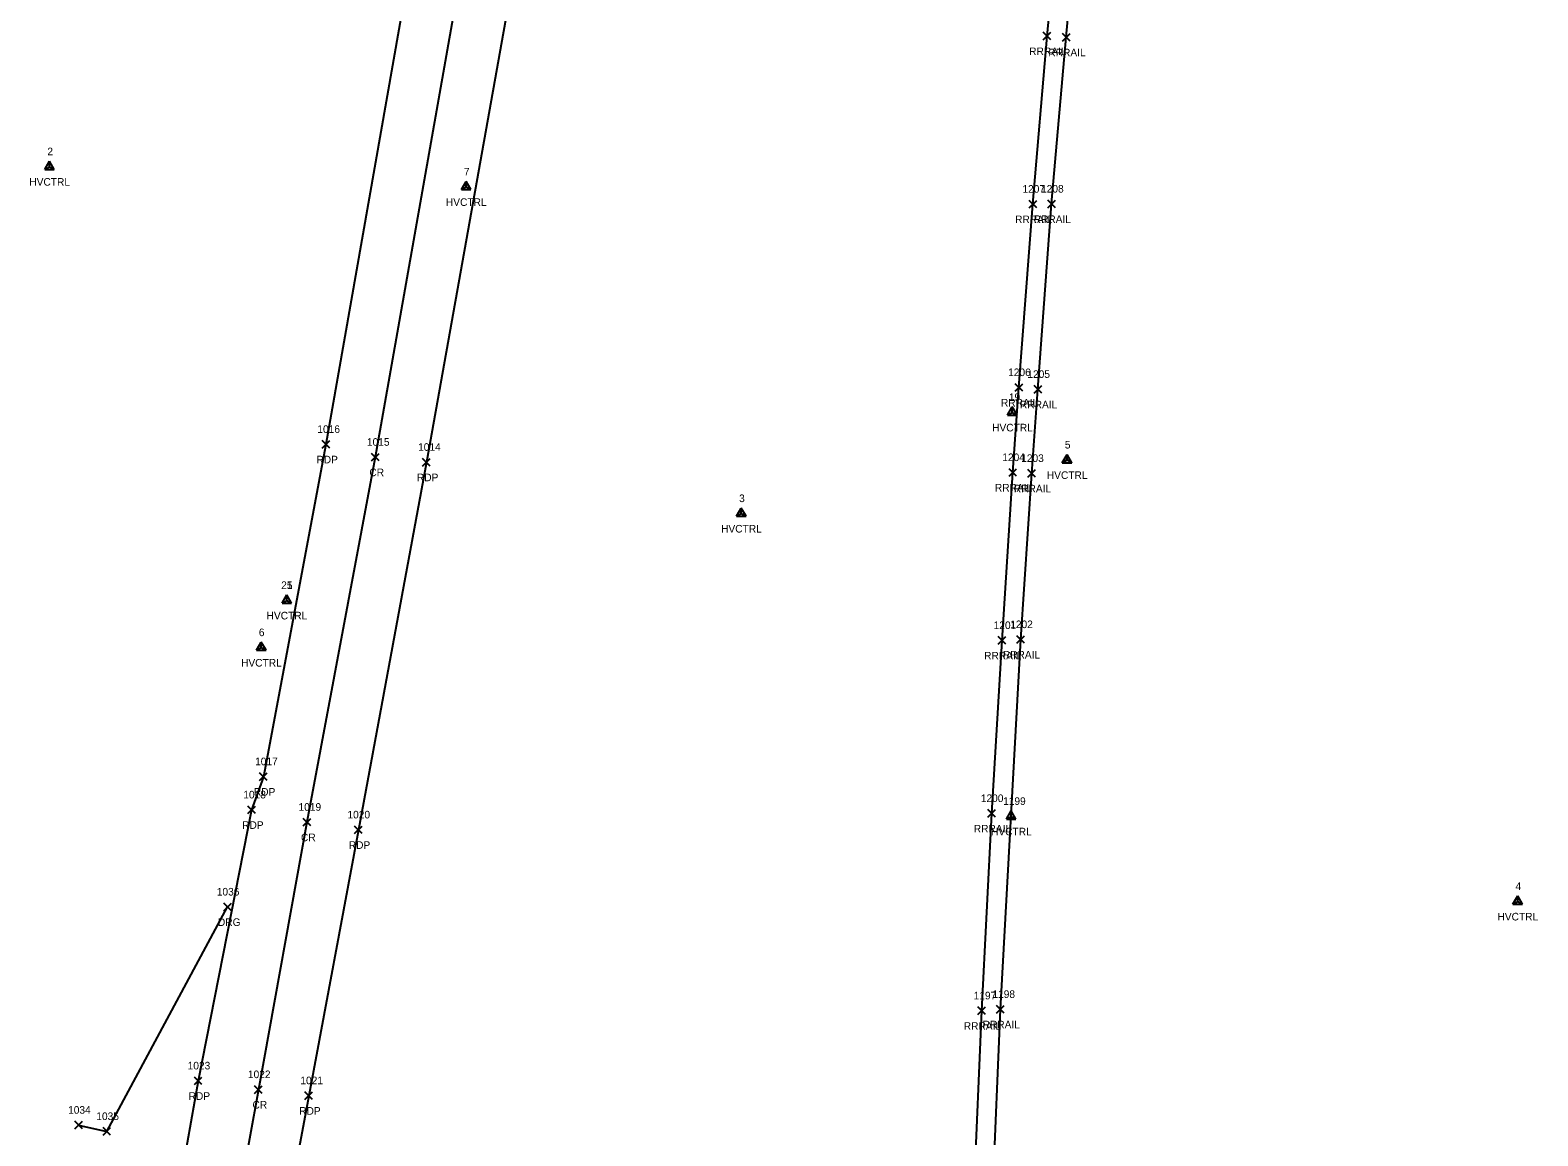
# Model space of a CAD drawing. Extents: x 1754529 to 1755810, y 621660 to 624656.
# Drawn here: x 1755360 to 1755756.4, y 623410 to 623700.7 of the extents above; entities that cross this region are included whole.
import ezdxf

# ---------------------------------------------------------------- set-up
doc = ezdxf.new("R2010")
doc.units = 0
for name, color, linetype in [('C_A', 7, 'Continuous'), ('C_I', 7, 'Continuous'), ('CPSM', 7, 'Continuous'), ('Level 14', 7, 'Continuous'), ('P_A', 7, 'Continuous'), ('P_I', 7, 'Continuous'), ('PET', 7, 'Continuous'), ('PRC', 7, 'Continuous'), ('R_A', 7, 'Continuous'), ('R_I', 7, 'Continuous'), ('R_TIC', 7, 'Continuous'), ('RDG', 7, 'Continuous'), ('RR', 7, 'Continuous')]:
    doc.layers.add(name, color=color, linetype=linetype)

msp = doc.modelspace()

# ---------------------------------------------------------------- linework, layer by layer
at = {"layer": 'CPSM'}
for p, q in [((1755363.86, 623664.07), (1755365.11, 623666.24)), ((1755363.86, 623664.07), (1755365.11, 623666.24)), ((1755366.36, 623664.07), (1755365.11, 623666.24)), ((1755365.12, 623664.79), (1755365.11, 623666.24)), ((1755366.36, 623664.07), (1755365.11, 623666.24)), ((1755365.12, 623664.79), (1755365.11, 623666.24)), ((1755363.86, 623664.07), (1755365.12, 623664.79)), ((1755363.86, 623664.07), (1755365.12, 623664.79)), ((1755363.86, 623664.07), (1755366.36, 623664.07)), ((1755363.86, 623664.07), (1755366.36, 623664.07)), ((1755365.12, 623664.79), (1755365.12, 623664.79)), ((1755365.12, 623664.79), (1755366.36, 623664.07)), ((1755365.12, 623664.79), (1755365.12, 623664.79)), ((1755365.12, 623664.79), (1755366.36, 623664.07)), ((1755473.39, 623658.75), (1755474.64, 623660.91)), ((1755473.39, 623658.75), (1755474.64, 623659.47)), ((1755473.39, 623658.75), (1755475.89, 623658.75)), ((1755475.89, 623658.75), (1755474.64, 623660.91)), ((1755474.64, 623659.47), (1755474.64, 623660.91)), ((1755474.64, 623659.47), (1755474.64, 623659.47)), ((1755474.64, 623659.47), (1755475.89, 623658.75)), ((1755617, 623599.48), (1755618.25, 623601.65)), ((1755617, 623599.48), (1755618.25, 623600.2)), ((1755617, 623599.48), (1755619.5, 623599.48)), ((1755619.5, 623599.48), (1755618.25, 623601.65)), ((1755618.25, 623600.2), (1755618.25, 623601.65)), ((1755618.25, 623600.2), (1755618.25, 623600.2)), ((1755618.25, 623600.2), (1755619.5, 623599.48)), ((1755631.38, 623586.98), (1755632.63, 623589.15)), ((1755631.38, 623586.98), (1755632.63, 623587.7)), ((1755631.38, 623586.98), (1755633.88, 623586.98)), ((1755633.88, 623586.98), (1755632.63, 623589.15)), ((1755632.63, 623587.7), (1755632.63, 623589.15)), ((1755632.63, 623587.7), (1755632.63, 623587.7)), ((1755632.63, 623587.7), (1755633.88, 623586.98)), ((1755545.73, 623572.9), (1755546.98, 623575.07)), ((1755548.23, 623572.9), (1755546.98, 623575.07)), ((1755546.98, 623573.63), (1755546.98, 623575.07)), ((1755545.73, 623572.9), (1755546.98, 623573.63)), ((1755545.73, 623572.9), (1755548.23, 623572.9)), ((1755546.98, 623573.63), (1755546.98, 623573.63)), ((1755546.98, 623573.63), (1755548.23, 623572.9)), ((1755426.24, 623550.06), (1755427.49, 623552.22)), ((1755426.26, 623550.07), (1755427.51, 623552.23)), ((1755426.26, 623550.07), (1755427.51, 623552.23)), ((1755426.26, 623550.07), (1755427.51, 623552.23)), ((1755426.26, 623550.07), (1755427.51, 623552.23)), ((1755426.26, 623550.07), (1755427.51, 623552.23)), ((1755428.74, 623550.06), (1755427.49, 623552.22)), ((1755427.49, 623550.78), (1755427.49, 623552.22)), ((1755428.76, 623550.07), (1755427.51, 623552.23)), ((1755427.51, 623550.79), (1755427.51, 623552.23)), ((1755428.76, 623550.07), (1755427.51, 623552.23)), ((1755427.51, 623550.79), (1755427.51, 623552.23)), ((1755428.76, 623550.07), (1755427.51, 623552.23)), ((1755427.51, 623550.79), (1755427.51, 623552.23)), ((1755428.76, 623550.07), (1755427.51, 623552.23)), ((1755427.51, 623550.79), (1755427.51, 623552.23)), ((1755428.76, 623550.07), (1755427.51, 623552.23)), ((1755427.51, 623550.79), (1755427.51, 623552.23)), ((1755426.24, 623550.06), (1755427.49, 623550.78)), ((1755426.24, 623550.06), (1755428.74, 623550.06)), ((1755426.26, 623550.07), (1755427.51, 623550.79)), ((1755426.26, 623550.07), (1755427.51, 623550.79)), ((1755426.26, 623550.07), (1755427.51, 623550.79)), ((1755426.26, 623550.07), (1755427.51, 623550.79)), ((1755426.26, 623550.07), (1755427.51, 623550.79)), ((1755426.26, 623550.07), (1755428.76, 623550.07)), ((1755426.26, 623550.07), (1755428.76, 623550.07)), ((1755426.26, 623550.07), (1755428.76, 623550.07)), ((1755426.26, 623550.07), (1755428.76, 623550.07)), ((1755426.26, 623550.07), (1755428.76, 623550.07)), ((1755427.49, 623550.78), (1755427.49, 623550.78)), ((1755427.49, 623550.78), (1755428.74, 623550.06)), ((1755427.51, 623550.79), (1755427.51, 623550.79)), ((1755427.51, 623550.79), (1755428.76, 623550.07)), ((1755427.51, 623550.79), (1755427.51, 623550.79)), ((1755427.51, 623550.79), (1755428.76, 623550.07)), ((1755427.51, 623550.79), (1755427.51, 623550.79)), ((1755427.51, 623550.79), (1755428.76, 623550.07)), ((1755427.51, 623550.79), (1755427.51, 623550.79)), ((1755427.51, 623550.79), (1755428.76, 623550.07)), ((1755427.51, 623550.79), (1755427.51, 623550.79)), ((1755427.51, 623550.79), (1755428.76, 623550.07)), ((1755419.54, 623537.66), (1755420.79, 623539.83)), ((1755422.04, 623537.66), (1755420.79, 623539.83)), ((1755420.79, 623538.38), (1755420.79, 623539.83)), ((1755419.54, 623537.66), (1755420.79, 623538.38)), ((1755419.54, 623537.66), (1755422.04, 623537.66)), ((1755420.79, 623538.38), (1755420.79, 623538.38)), ((1755420.79, 623538.38), (1755422.04, 623537.66)), ((1755616.71, 623493.3), (1755617.96, 623495.46)), ((1755619.21, 623493.3), (1755617.96, 623495.46)), ((1755617.96, 623494.02), (1755617.96, 623495.46)), ((1755616.71, 623493.3), (1755617.96, 623494.02)), ((1755616.71, 623493.3), (1755619.21, 623493.3)), ((1755617.96, 623494.02), (1755617.96, 623494.02)), ((1755617.96, 623494.02), (1755619.21, 623493.3)), ((1755749.86, 623470.94), (1755751.11, 623473.1)), ((1755749.86, 623470.94), (1755751.11, 623471.66)), ((1755752.36, 623470.94), (1755751.11, 623473.1)), ((1755751.11, 623471.66), (1755751.11, 623473.1)), ((1755751.11, 623471.66), (1755751.11, 623471.66)), ((1755751.11, 623471.66), (1755752.36, 623470.94)), ((1755749.86, 623470.94), (1755752.36, 623470.94))]:
    msp.add_line(p, q, dxfattribs=at)
at = {"layer": 'Level 14'}
for points in [[(1755436.79, 623590.8), (1755438.79, 623592.8)], [(1755438.79, 623590.8), (1755436.79, 623592.8)], [(1755449.77, 623587.43), (1755451.77, 623589.43)], [(1755451.77, 623587.43), (1755449.77, 623589.43)], [(1755463.22, 623586.1), (1755465.22, 623588.1)], [(1755465.22, 623586.1), (1755463.22, 623588.1)], [(1755420.36, 623503.45), (1755422.36, 623505.45)], [(1755422.36, 623503.45), (1755420.36, 623505.45)], [(1755417.26, 623494.73), (1755419.26, 623496.73)], [(1755419.26, 623494.73), (1755417.26, 623496.73)], [(1755431.8, 623491.49), (1755433.8, 623493.49)], [(1755433.8, 623491.49), (1755431.8, 623493.49)], [(1755445.31, 623489.47), (1755447.31, 623491.47)], [(1755447.31, 623489.47), (1755445.31, 623491.47)], [(1755403.2, 623423.5), (1755405.2, 623425.5)], [(1755405.2, 623423.5), (1755403.2, 623425.5)], [(1755419.05, 623421.21), (1755421.05, 623423.21)], [(1755421.05, 623421.21), (1755419.05, 623423.21)], [(1755432.28, 623419.6), (1755434.28, 623421.6)], [(1755434.28, 623419.6), (1755432.28, 623421.6)]]:
    msp.add_lwpolyline(points, dxfattribs=at)
at = {"layer": 'PET'}
for points in [[(1755535.07, 624132.59), (1755507.27, 623983.72), (1755476.9, 623815.46), (1755460.3, 623719.87), (1755437.79, 623591.8), (1755421.36, 623504.45), (1755418.26, 623495.73), (1755404.2, 623424.5), (1755397.43, 623386.49), (1755390.98, 623344.71), (1755391.72, 623340.77), (1755385.02, 623296.56), (1755379.33, 623252.08), (1755376.53, 623216.25), (1755375.95, 623174.43), (1755377.19, 623132.58)], [(1755561.91, 624125.77), (1755533.66, 623976.91), (1755504.04, 623811.48), (1755486.8, 623713.65), (1755464.22, 623587.1), (1755446.31, 623490.47), (1755433.28, 623420.6), (1755425.75, 623380.35), (1755417.64, 623332.29), (1755411.38, 623292.51), (1755405.94, 623251.45), (1755403.49, 623215.07), (1755403.14, 623175.05), (1755404.1, 623131.29)]]:
    msp.add_lwpolyline(points, dxfattribs=at)
at = {"layer": 'PRC'}
msp.add_lwpolyline([(1755548.82, 624129.6), (1755520.89, 623980.45), (1755490.93, 623813.93), (1755473.47, 623716.78), (1755450.77, 623588.43), (1755432.8, 623492.49), (1755420.05, 623422.21), (1755412.93, 623383.28), (1755404.64, 623333.82), (1755398.35, 623294.75), (1755393.11, 623251.83), (1755390.3, 623215.98), (1755389.28, 623175.01), (1755390.29, 623132.74)], dxfattribs=at)
at = {"layer": 'R_TIC'}
for points in [[(1755626.39, 623698.11), (1755628.39, 623700.11)], [(1755628.39, 623698.11), (1755626.39, 623700.11)], [(1755631.43, 623697.79), (1755633.43, 623699.79)], [(1755633.43, 623697.79), (1755631.43, 623699.79)], [(1755622.67, 623653.94), (1755624.67, 623655.94)], [(1755624.67, 623653.94), (1755622.67, 623655.94)], [(1755627.57, 623653.98), (1755629.57, 623655.98)], [(1755629.57, 623653.98), (1755627.57, 623655.98)], [(1755618.97, 623605.74), (1755620.97, 623607.74)], [(1755620.97, 623605.74), (1755618.97, 623607.74)], [(1755623.97, 623605.26), (1755625.97, 623607.26)], [(1755625.97, 623605.26), (1755623.97, 623607.26)], [(1755617.38, 623583.4), (1755619.38, 623585.4)], [(1755619.38, 623583.4), (1755617.38, 623585.4)], [(1755622.35, 623583.17), (1755624.35, 623585.17)], [(1755624.35, 623583.17), (1755622.35, 623585.17)], [(1755614.55, 623539.26), (1755616.55, 623541.26)], [(1755616.55, 623539.26), (1755614.55, 623541.26)], [(1755619.46, 623539.5), (1755621.46, 623541.5)], [(1755621.46, 623539.5), (1755619.46, 623541.5)], [(1755611.83, 623493.78), (1755613.83, 623495.78)], [(1755613.83, 623493.78), (1755611.83, 623495.78)], [(1755410.92, 623469.21), (1755412.92, 623471.21)], [(1755412.92, 623469.21), (1755410.92, 623471.21)], [(1755609.2, 623441.91), (1755611.2, 623443.91)], [(1755611.2, 623441.91), (1755609.2, 623443.91)], [(1755614.13, 623442.29), (1755616.13, 623444.29)], [(1755616.13, 623442.29), (1755614.13, 623444.29)], [(1755371.77, 623411.86), (1755373.77, 623413.86)], [(1755373.77, 623411.86), (1755371.77, 623413.86)], [(1755379.19, 623410.2), (1755381.19, 623412.2)], [(1755381.19, 623410.2), (1755379.19, 623412.2)]]:
    msp.add_lwpolyline(points, dxfattribs=at)
at = {"layer": 'RDG'}
msp.add_lwpolyline([(1755372.77, 623412.86), (1755380.19, 623411.2), (1755411.92, 623470.21)], dxfattribs=at)
at = {"layer": 'RR'}
for points in [[(1755604.49, 623127.28), (1755604.22, 623170.71), (1755604.28, 623211.65), (1755604.62, 623254.04), (1755605.32, 623298.27), (1755606.47, 623346.99), (1755608.24, 623395.75), (1755610.2, 623442.91), (1755612.83, 623494.78), (1755615.55, 623540.26), (1755618.38, 623584.4), (1755619.97, 623606.74), (1755623.67, 623654.94), (1755627.39, 623699.11), (1755631.78, 623745.19)], [(1755609.4, 623127.16), (1755609.16, 623170.67), (1755609.26, 623211.62), (1755609.56, 623254.58), (1755610.19, 623298.31), (1755611.51, 623347.53), (1755613.11, 623395.25), (1755615.13, 623443.29), (1755620.46, 623540.5), (1755623.35, 623584.17), (1755624.97, 623606.26), (1755628.57, 623654.98), (1755632.43, 623698.79), (1755636.73, 623745.2)]]:
    msp.add_lwpolyline(points, dxfattribs=at)

# ---------------------------------------------------------------- texts
at = {"layer": 'C_A'}
for p in [(1755359.81, 623659.79), (1755359.81, 623659.79), (1755469.33, 623654.47), (1755612.94, 623595.2), (1755627.32, 623582.7), (1755541.68, 623568.62), (1755422.18, 623545.78), (1755422.2, 623545.79), (1755422.2, 623545.79), (1755422.2, 623545.79), (1755422.2, 623545.79), (1755422.2, 623545.79), (1755415.48, 623533.38), (1755612.65, 623489.02), (1755745.8, 623466.66)]:
    msp.add_text('HVCTRL', height=2, dxfattribs=at).set_placement(p)
at = {"layer": 'C_I'}
for s, p in [('2', (1755364.55, 623667.79)), ('2', (1755364.55, 623667.79)), ('7', (1755474.07, 623662.47)), ('19', (1755617.34, 623603.2)), ('5', (1755632.06, 623590.7)), ('3', (1755546.42, 623576.62)), ('25', (1755426.02, 623553.78)), ('1', (1755427.51, 623553.79)), ('1', (1755427.51, 623553.79)), ('1', (1755427.51, 623553.79)), ('1', (1755427.51, 623553.79)), ('1', (1755427.51, 623553.79)), ('6', (1755420.16, 623541.38)), ('1199', (1755615.82, 623497.02)), ('4', (1755750.54, 623474.66))]:
    msp.add_text(s, height=2, dxfattribs=at).set_placement(p)
at = {"layer": 'P_A'}
for s, p in [('RDP', (1755435.28, 623586.8)), ('CR', (1755449.21, 623583.43)), ('RDP', (1755461.71, 623582.1)), ('RDP', (1755418.85, 623499.45)), ('RDP', (1755415.75, 623490.73)), ('CR', (1755431.23, 623487.49)), ('RDP', (1755443.79, 623485.47)), ('RDP', (1755401.69, 623419.5)), ('CR', (1755418.49, 623417.21)), ('RDP', (1755430.76, 623415.6))]:
    msp.add_text(s, height=2, dxfattribs=at).set_placement(p)
at = {"layer": 'P_I'}
for s, p in [('1016', (1755435.53, 623594.8)), ('1015', (1755448.57, 623591.43)), ('1014', (1755462.02, 623590.1)), ('1017', (1755419.16, 623507.45)), ('1018', (1755416.06, 623498.73)), ('1019', (1755430.58, 623495.49)), ('1020', (1755443.45, 623493.47)), ('1023', (1755401.43, 623427.5)), ('1022', (1755417.28, 623425.21)), ('1021', (1755431.07, 623423.6))]:
    msp.add_text(s, height=2, dxfattribs=at).set_placement(p)
at = {"layer": 'R_A'}
for s, p in [('RRRAIL', (1755622.68, 623694.11)), ('RRRAIL', (1755627.72, 623693.79)), ('RRRAIL', (1755618.97, 623649.94)), ('RRRAIL', (1755623.86, 623649.98)), ('RRRAIL', (1755615.26, 623601.74)), ('RRRAIL', (1755620.26, 623601.26)), ('RRRAIL', (1755613.67, 623579.4)), ('RRRAIL', (1755618.65, 623579.17)), ('RRRAIL', (1755610.84, 623535.26)), ('RRRAIL', (1755615.75, 623535.5)), ('RRRAIL', (1755608.12, 623489.78)), ('DRG', (1755409.4, 623465.21)), ('RRRAIL', (1755605.49, 623437.91)), ('RRRAIL', (1755610.43, 623438.29))]:
    msp.add_text(s, height=2, dxfattribs=at).set_placement(p)
at = {"layer": 'R_I'}
for s, p in [('1207', (1755620.9, 623657.94)), ('1208', (1755625.8, 623657.98)), ('1206', (1755617.14, 623609.74)), ('1205', (1755622.2, 623609.26)), ('1204', (1755615.61, 623587.4)), ('1203', (1755620.58, 623587.17)), ('1201', (1755613.34, 623543.26)), ('1202', (1755617.69, 623543.5)), ('1200', (1755609.97, 623497.78)), ('1036', (1755409.09, 623473.21)), ('1197', (1755608.08, 623445.91)), ('1198', (1755613.01, 623446.29)), ('1034', (1755370, 623415.86)), ('1035', (1755377.42, 623414.2))]:
    msp.add_text(s, height=2, dxfattribs=at).set_placement(p)

doc.saveas('drawing.dxf')
